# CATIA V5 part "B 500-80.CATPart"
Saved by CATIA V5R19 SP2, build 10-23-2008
Part number: B 500-80
Bounding box of the stored display mesh (mm): x -18.951 to 18.951, y -18.952 to 18.952, z 0 to 210
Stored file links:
  C:\Users\Bora\Desktop\3D Katı model\B serisi\B 500\B 500-80.CATPart
  C:\Program Files\Dassault Systemes\B19\intel_a\reffiles\standard\MetricThickPitch.txt
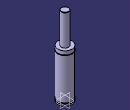
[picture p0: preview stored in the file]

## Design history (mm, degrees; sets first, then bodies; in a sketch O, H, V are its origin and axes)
Body1 (main body)
  Sketch1 on yz-plane, origin (0, 0, 0), H (0, 1, 0), V (0, 0, 1)
    point P1 (19, 118.5)
    point P4 (19, 116.5)
    point P7 (19, 118.5)
    point P8 (19, 116.5)
    point P9 (10, 209)
    point P11 (10, 209)
    line L1 (19, 118.5) -> (19, 128)
    line L2 (19, 7.5) -> (19, 116.5)
    line L3 (16.5, 7.5) -> (16.5, 4)
    arc A1 centre (19, 117.5) radius 1 from (19, 118.5) to (19, 116.5) ccw
    arc A2 centre (9, 209) radius 1 from (10, 209) to (9, 210) ccw
    line L4 (10, 209) -> (10, 128)
    line L5 (19, 0) -> (19, 4)
    line L6 (9, 210) -> (0, 210)
    point P15 (0, 210)
    line L7 (10, 128) -> (19, 128)
    line L8 (0, 0) -> (19, 0)
    line L9 (16.5, 7.5) -> (19, 7.5)
    line L10 (16.5, 4) -> (19, 4)
    coincidence: P15 V, P1 P7, P4 P8, P9 P11
    tangency: L6 A2
    horizontal: L7 H, L8 H, L9 H, L10 H
  Shaft1: profile Sketch1, axis Sketch1.V, angle 360
  Sketch2 on face of Shaft1 from Sketch1.L8, origin (0, 0, 0), H (1, 0, 0), V (0, -1, 0)
    point P1 (0, 0)
  Hole1: placed by Sketch2, at (0, 0, 0) direction (0, 0, 1), diameter 6.647, depth 7, threaded "M8", thread diameter 8, thread depth 7, pitch 1.25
